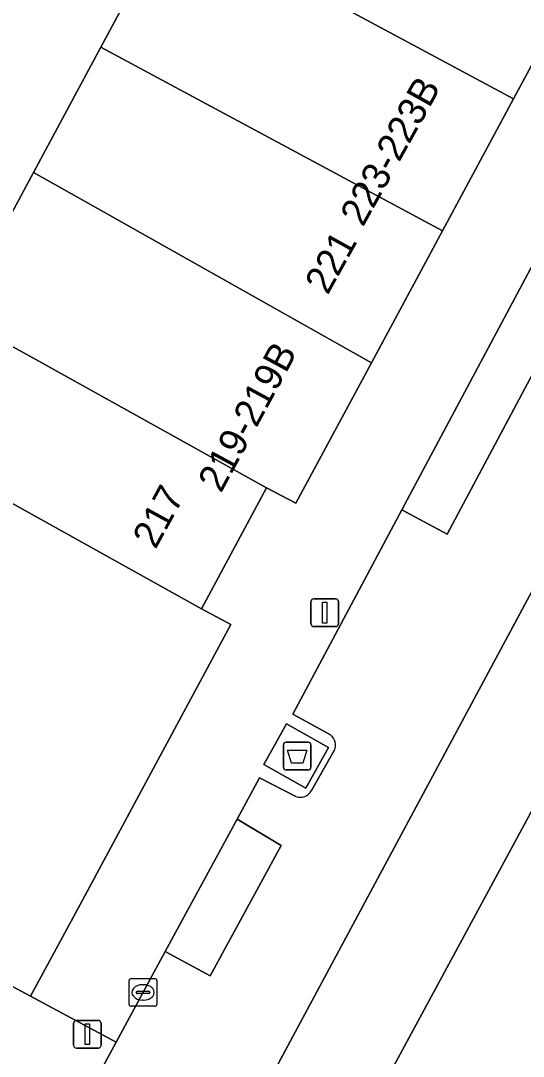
# Model space of a CAD drawing. Extents: x 159489 to 160304, y 383825 to 384531.
# Drawn here: x 159795.96 to 159814.07, y 384022.53 to 384059.86 of the extents above; entities that cross this region are included whole.
import ezdxf

# ---------------------------------------------------------------- set-up
doc = ezdxf.new("R2010")
doc.units = 0
for name, color, linetype in [('IMGEO_Afval_apart_plaats', 7, 'Continuous'), ('IMGEO_Berm_groen', 7, 'Continuous'), ('IMGEO_Erf', 7, 'Continuous'), ('IMGEO_Kolk', 7, 'Continuous'), ('IMGEO_Lichtmast', 7, 'Continuous'), ('IMGEO_OVBaan_gesloten', 7, 'Continuous'), ('IMGEO_Pand', 7, 'Continuous'), ('IMGEO_Pand_nummerreeks', 7, 'Continuous'), ('IMGEO_Parkeervlak_gesloten', 7, 'Continuous'), ('IMGEO_Rijbaan_lokaal_gesloten', 7, 'Continuous'), ('IMGEO_Voetpad_gesloten', 7, 'Continuous'), ('IMGEO_Voetpad_open', 7, 'Continuous')]:
    doc.layers.add(name, color=color, linetype=linetype)

msp = doc.modelspace()

# ---------------------------------------------------------------- linework, layer by layer
at = {"layer": 'IMGEO_Afval_apart_plaats'}
for p, q in [((159805.524, 384033.855), (159806.314, 384033.855)), ((159806.314, 384033.855), (159805.524, 384033.855)), ((159805.424, 384032.955), (159805.424, 384033.755)), ((159805.424, 384033.755), (159805.424, 384032.955)), ((159806.414, 384033.755), (159806.414, 384032.955)), ((159806.414, 384032.955), (159806.414, 384033.755)), ((159806.314, 384032.855), (159805.524, 384032.855)), ((159805.524, 384032.855), (159806.314, 384032.855))]:
    msp.add_line(p, q, dxfattribs=at)
msp.add_lwpolyline([(159805.567, 384033.569), (159806.271, 384033.569), (159806.122, 384033.099), (159805.716, 384033.099), (159805.567, 384033.569)], dxfattribs=at)
for centre, start, end in [((159805.524, 384033.755), 90, 180), ((159805.524, 384033.755), 90, 180), ((159806.314, 384033.755), 0, 90), ((159806.314, 384033.755), 360, 90), ((159805.524, 384032.955), 180, 270), ((159805.524, 384032.955), 180, 270), ((159806.314, 384032.955), 270, 0), ((159806.314, 384032.955), 270, 0)]:
    msp.add_arc(centre, 0.1, start, end, dxfattribs=at)
at = {"layer": 'IMGEO_Berm_groen'}
msp.add_lwpolyline([(159844.928, 384088.249), (159841.694, 384089.989), (159825.877, 384060.739), (159803.412, 384018.855), (159803.036, 384018.159), (159806.279, 384016.403), (159815.461, 384033.388), (159819.297, 384040.613)], close=True, dxfattribs=at)
at = {"layer": 'IMGEO_Erf'}
msp.add_lwpolyline([(159766.267, 384056.759), (159771.029, 384054.198), (159775.785, 384051.64), (159780.536, 384049.085), (159785.098, 384046.631), (159784.572, 384045.652), (159791.189, 384042.093), (159792.356, 384044.263), (159794.711, 384048.642), (159793.646, 384049.235), (159796.419, 384054.39), (159798.849, 384058.909), (159801.215, 384063.308)], dxfattribs=at)
at = {"layer": 'IMGEO_Kolk'}
for p, q in [((159799.865, 384024.406), (159799.865, 384025.258)), ((159799.94, 384025.332), (159800.792, 384025.332)), ((159800.866, 384025.258), (159800.866, 384024.406)), ((159800.353, 384025.112), (159800.378, 384025.112)), ((159800.124, 384024.826), (159800.124, 384024.838)), ((159800.562, 384024.789), (159800.164, 384024.789)), ((159800.167, 384024.875), (159800.565, 384024.875)), ((159800.376, 384024.552), (159800.351, 384024.552)), ((159800.608, 384024.838), (159800.608, 384024.826)), ((159800.792, 384024.332), (159799.94, 384024.332))]:
    msp.add_line(p, q, dxfattribs=at)
for points in [[(159799.865, 384024.406), (159799.865, 384025.258)], [(159799.94, 384025.332), (159800.792, 384025.332)], [(159800.866, 384025.258), (159800.866, 384024.406)], [(159800.792, 384024.332), (159799.94, 384024.332)]]:
    msp.add_lwpolyline(points, dxfattribs=at)
for centre, radius, start, end in [((159799.942, 384025.256), 0.0765, 91.552, 178.448), ((159799.942, 384025.256), 0.0765, 91.552, 178.448), ((159800.79, 384025.256), 0.0765, 1.552, 88.448), ((159800.79, 384025.256), 0.0765, 1.552, 88.448), ((159800.164, 384024.835), 0.0403, 85.8775, 175.7526), ((159800.161, 384024.825), 0.0366, 178.938, 274.7102), ((159800.565, 384024.832), 0.043, 264.8664, 352.4533), ((159800.569, 384024.837), 0.0386, 1.7309, 96.639), ((159799.942, 384024.408), 0.0765, 181.552, 268.448), ((159799.942, 384024.408), 0.0765, 181.552, 268.448), ((159800.79, 384024.408), 0.0765, 271.552, 358.448), ((159800.79, 384024.408), 0.0765, 271.552, 358.448)]:
    msp.add_arc(centre, radius, start, end, dxfattribs=at)
for centre, major_axis, ratio, start_param, end_param in [((159800.352, 384024.832), (-0.387, 0.002), 0.722429, 4.712389, 7.853982), ((159800.377, 384024.832), (-0.39, 0.002), 0.717154, 1.570796, 4.712389)]:
    msp.add_ellipse(centre, major_axis=major_axis, ratio=ratio, start_param=start_param, end_param=end_param, dxfattribs=at)
at = {"layer": 'IMGEO_Lichtmast'}
for p, q in [((159806.416, 384038.122), (159806.416, 384038.922)), ((159806.416, 384038.922), (159806.416, 384038.122)), ((159806.516, 384039.022), (159807.306, 384039.022)), ((159807.306, 384039.022), (159806.516, 384039.022)), ((159807.406, 384038.922), (159807.406, 384038.122)), ((159807.406, 384038.122), (159807.406, 384038.922)), ((159807.306, 384038.022), (159806.516, 384038.022)), ((159806.516, 384038.022), (159807.306, 384038.022)), ((159797.965, 384023.826), (159798.755, 384023.826)), ((159798.755, 384023.826), (159797.965, 384023.826)), ((159797.865, 384022.926), (159797.865, 384023.726)), ((159797.865, 384023.726), (159797.865, 384022.926)), ((159798.855, 384023.726), (159798.855, 384022.926)), ((159798.855, 384022.926), (159798.855, 384023.726)), ((159798.755, 384022.826), (159797.965, 384022.826)), ((159797.965, 384022.826), (159798.755, 384022.826))]:
    msp.add_line(p, q, dxfattribs=at)
for points in [[(159806.836, 384038.897), (159806.986, 384038.897), (159806.986, 384038.147), (159806.836, 384038.147), (159806.836, 384038.897)], [(159798.285, 384023.701), (159798.435, 384023.701), (159798.435, 384022.951), (159798.285, 384022.951), (159798.285, 384023.701)]]:
    msp.add_lwpolyline(points, dxfattribs=at)
for centre, start, end in [((159806.516, 384038.922), 90, 180), ((159806.516, 384038.922), 90, 180), ((159807.306, 384038.922), 0, 90), ((159807.306, 384038.922), 360, 90), ((159806.516, 384038.122), 180, 270), ((159806.516, 384038.122), 180, 270), ((159807.306, 384038.122), 270, 0), ((159807.306, 384038.122), 270, 0), ((159797.965, 384023.726), 90, 180), ((159797.965, 384023.726), 90, 180), ((159798.755, 384023.726), 0, 90), ((159798.755, 384023.726), 360, 90), ((159797.965, 384022.926), 180, 270), ((159797.965, 384022.926), 180, 270), ((159798.755, 384022.926), 270, 0), ((159798.755, 384022.926), 270, 0)]:
    msp.add_arc(centre, 0.1, start, end, dxfattribs=at)
at = {"layer": 'IMGEO_OVBaan_gesloten'}
msp.add_lwpolyline([(159821.217, 384030.334), (159822.613, 384032.7), (159825.117, 384037.509), (159819.297, 384040.613), (159815.461, 384033.388), (159806.279, 384016.403), (159805.225, 384014.454), (159804.049, 384012.761), (159802.971, 384011.597), (159809.37, 384007.908), (159810.974, 384011.376), (159812.088, 384013.422)], close=True, dxfattribs=at)
at = {"layer": 'IMGEO_Pand'}
for points in [[(159805.565, 384082.24), (159805.24, 384082.416), (159800.234, 384073.149), (159799.942, 384073.305), (159799.545, 384072.565), (159805.621, 384069.422), (159802.082, 384062.843), (159802.928, 384062.389), (159803.121, 384062.744), (159813.711, 384057.051), (159816.172, 384061.629), (159819.714, 384068.212), (159822.364, 384073.19), (159821.062, 384073.891), (159811.752, 384078.907)], [(159803.121, 384062.744), (159802.928, 384062.389), (159802.082, 384062.843), (159801.215, 384063.308), (159798.849, 384058.909), (159800.561, 384057.988), (159811.153, 384052.293), (159813.711, 384057.051)], [(159800.561, 384057.988), (159798.849, 384058.909), (159796.419, 384054.39), (159798.091, 384053.448), (159808.594, 384047.531), (159811.153, 384052.293)], [(159808.594, 384047.531), (159798.091, 384053.448), (159796.419, 384054.39), (159793.646, 384049.235), (159794.711, 384048.642), (159795.323, 384048.301), (159796.285, 384047.766), (159804.812, 384043.02), (159805.871, 384042.465)], [(159796.285, 384047.766), (159795.323, 384048.301), (159794.711, 384048.642), (159792.356, 384044.263), (159793.941, 384043.41), (159802.47, 384038.666), (159804.812, 384043.02)], [(159778.666, 384034.176), (159785.645, 384030.424), (159785.732, 384030.559), (159790.367, 384028.077), (159790.874, 384027.608), (159796.313, 384024.693), (159797.928, 384027.689), (159803.527, 384038.097), (159802.47, 384038.666), (159793.941, 384043.41), (159792.356, 384044.263), (159791.189, 384042.093), (159784.572, 384045.652), (159784.211, 384044.994), (159784.42, 384044.886)]]:
    msp.add_lwpolyline(points, close=True, dxfattribs=at)
at = {"layer": 'IMGEO_Parkeervlak_gesloten'}
for points in [[(159833.197, 384085.844), (159819.995, 384061.553), (159809.693, 384042.226), (159811.322, 384041.358), (159821.621, 384060.678), (159834.394, 384084.181), (159834.819, 384084.963)], [(159805.339, 384030.131), (159803.752, 384031.078), (159801.167, 384026.309), (159802.79, 384025.429)]]:
    msp.add_lwpolyline(points, close=True, dxfattribs=at)
at = {"layer": 'IMGEO_Rijbaan_lokaal_gesloten'}
for points in [[(159805.875, 384031.899), (159804.558, 384032.564), (159803.752, 384031.078), (159805.339, 384030.131), (159802.79, 384025.429), (159801.167, 384026.309), (159799.393, 384023.037), (159797.098, 384018.803), (159801.988, 384016.22), (159803.036, 384018.159), (159803.412, 384018.855), (159825.877, 384060.739), (159841.694, 384089.989)], [(159835.051, 384085.907), (159833.649, 384086.676), (159833.197, 384085.844), (159834.819, 384084.963), (159834.394, 384084.181), (159821.621, 384060.678), (159811.322, 384041.358), (159809.693, 384042.226), (159805.766, 384034.859), (159807.126, 384034.114)], [(159807.255, 384033.557), (159806.434, 384032.107)]]:
    msp.add_lwpolyline(points, dxfattribs=at)
for centre, radius, start, end in [((159806.863, 384033.76), 0.441, 332.6471, 53.4323), ((159806.037, 384032.318), 0.45, 248.8647, 331.955)]:
    msp.add_arc(centre, radius, start, end, dxfattribs=at)
at = {"layer": 'IMGEO_Voetpad_gesloten'}
msp.add_lwpolyline([(159807.054, 384033.662), (159805.535, 384034.511), (159804.716, 384033.045), (159806.235, 384032.196)], close=True, dxfattribs=at)
at = {"layer": 'IMGEO_Voetpad_open'}
for points in [[(159834.642, 384096.101), (159828.467, 384084.527), (159826.63, 384081.083), (159826.448, 384081.181), (159825.719, 384079.87), (159825.936, 384079.753), (159824.035, 384076.271), (159822.364, 384073.19), (159819.714, 384068.212), (159820.789, 384067.656), (159817.243, 384061.099), (159816.172, 384061.629), (159813.711, 384057.051), (159811.153, 384052.293), (159808.594, 384047.531), (159805.871, 384042.465), (159804.812, 384043.02), (159802.47, 384038.666), (159803.527, 384038.097), (159797.928, 384027.689), (159796.313, 384024.693), (159799.393, 384023.037), (159801.167, 384026.309), (159803.752, 384031.078)], [(159807.126, 384034.114), (159805.766, 384034.859), (159809.693, 384042.226), (159819.995, 384061.553), (159833.197, 384085.844), (159833.649, 384086.676), (159835.051, 384085.907)], [(159806.434, 384032.107), (159807.255, 384033.557)], [(159803.752, 384031.078), (159804.558, 384032.564), (159805.875, 384031.899)]]:
    msp.add_lwpolyline(points, dxfattribs=at)
for points in [[(159748.885, 384052.879), (159745.177, 384054.872), (159744.059, 384052.782), (159744, 384052.814), (159737.293, 384056.412), (159733.379, 384058.49), (159731.166, 384054.292), (159797.098, 384018.803), (159799.393, 384023.037), (159796.313, 384024.693), (159790.874, 384027.608), (159790.367, 384028.077), (159785.732, 384030.559), (159785.645, 384030.424), (159778.666, 384034.176), (159773.904, 384036.736), (159769.137, 384039.299), (159764.388, 384041.852), (159759.654, 384044.398), (159754.877, 384046.966), (159747.838, 384050.751), (159747.763, 384050.791)], [(159804.716, 384033.045), (159805.535, 384034.511), (159807.054, 384033.662), (159806.235, 384032.196)]]:
    msp.add_lwpolyline(points, close=True, dxfattribs=at)
for centre, radius, start, end in [((159806.863, 384033.76), 0.441, 332.6471, 53.4323), ((159806.037, 384032.318), 0.45, 248.8647, 331.955)]:
    msp.add_arc(centre, radius, start, end, dxfattribs=at)

# ---------------------------------------------------------------- texts
at = {"layer": 'IMGEO_Pand_nummerreeks'}
for s, rotation, p in [('223-223B', 60.8768, (159808.291, 384052.399)), ('221', 60.9799, (159807.021, 384049.948)), ('219-219B', 61.5758, (159803.176, 384042.808)), ('217', 61.3982, (159800.817, 384040.777))]:
    msp.add_text(s, height=1, rotation=rotation, dxfattribs=at).set_placement(p)

doc.saveas('drawing.dxf')
